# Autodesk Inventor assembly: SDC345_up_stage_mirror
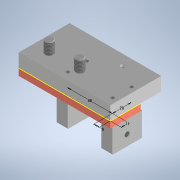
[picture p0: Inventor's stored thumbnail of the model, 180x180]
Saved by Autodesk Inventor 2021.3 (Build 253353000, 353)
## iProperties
Created: 2022-02
Part Number: SDC345_up_stage_mirror
Document SubType Name: Assembly
Designer: kengo
Author: kengo
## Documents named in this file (6)
- C:\Users\kengo\Documents\S2S_frame\SDC345\frame_misumi_ver12\upper-stage\SDC345_up_stage_mirror.iam
- C:\Users\kengo\Documents\S2S_frame\SDC345\frame_misumi_ver12\upper-stage\SDC_upper_stage_AlPlate_mirror.ipt
- C:\Users\kengo\Documents\S2S_frame\SDC345\frame_misumi_ver12\upper-stage\CBM12-25.ipt
- C:\Users\kengo\Documents\S2S_frame\SDC345\frame_misumi_ver12\upper-stage\SDC_upper_stage_CFPlate.ipt
- C:\Users\kengo\Documents\S2S_frame\SDC345\frame_misumi_ver12\upper-stage\AJSN8-20.ipt
- C:\Users\kengo\Documents\S2S_frame\SDC345\frame_misumi_ver12\upper-stage\SCB6-55.ipt
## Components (10 placed, 5 different names)
1. SDC_upper_stage_AlPlate_mirror:1 — 回転:1, 回転:2, メイト:1, フラッシュ:1, フラッシュ:2
2. CBM12-25:1 — 回転:1
3. CBM12-25:2 — 回転:2
4. SDC_upper_stage_CFPlate:1 — メイト:1, フラッシュ:1, フラッシュ:2, メイト:2, フラッシュ:3, 挿入:1, メイト:3, 挿入:2, 挿入:3
5. AJSN8-20:1 — メイト:2, フラッシュ:3, 挿入:1, リジッド:1, 回転:3
6. AJSN8-20:2 — メイト:3, 挿入:2, 挿入:3, 回転:4, 回転:5
7. SCB6-55:1 — リジッド:1
8. SCB6-55:2 — 回転:3
9. SCB6-55:3 — 回転:4
10. SCB6-55:4 — 回転:5
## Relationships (15: RevoluteJoint 5, Mate 3, Flush 3, Insert 3, WeldJoint 1)
- 回転:1 [RevoluteJoint]: SDC_upper_stage_AlPlate_mirror:1 ↔ CBM12-25:1
- 回転:2 [RevoluteJoint]: SDC_upper_stage_AlPlate_mirror:1 ↔ CBM12-25:2
- メイト:1 [Mate]: SDC_upper_stage_AlPlate_mirror:1 ↔ SDC_upper_stage_CFPlate:1
- フラッシュ:1 [Flush]: SDC_upper_stage_AlPlate_mirror:1 ↔ SDC_upper_stage_CFPlate:1
- フラッシュ:2 [Flush]: SDC_upper_stage_AlPlate_mirror:1 ↔ SDC_upper_stage_CFPlate:1
- メイト:2 [Mate]: SDC_upper_stage_CFPlate:1 ↔ AJSN8-20:1
- フラッシュ:3 [Flush]: SDC_upper_stage_CFPlate:1 ↔ AJSN8-20:1
- 挿入:1 [Insert]: SDC_upper_stage_CFPlate:1 ↔ AJSN8-20:1
- メイト:3 [Mate]: SDC_upper_stage_CFPlate:1 ↔ AJSN8-20:2
- 挿入:2 [Insert]: SDC_upper_stage_CFPlate:1 ↔ AJSN8-20:2
- 挿入:3 [Insert]: SDC_upper_stage_CFPlate:1 ↔ AJSN8-20:2
- リジッド:1 [WeldJoint]: AJSN8-20:1 ↔ SCB6-55:1
- 回転:3 [RevoluteJoint]: AJSN8-20:1 ↔ SCB6-55:2
- 回転:4 [RevoluteJoint]: AJSN8-20:2 ↔ SCB6-55:3
- 回転:5 [RevoluteJoint]: AJSN8-20:2 ↔ SCB6-55:4
